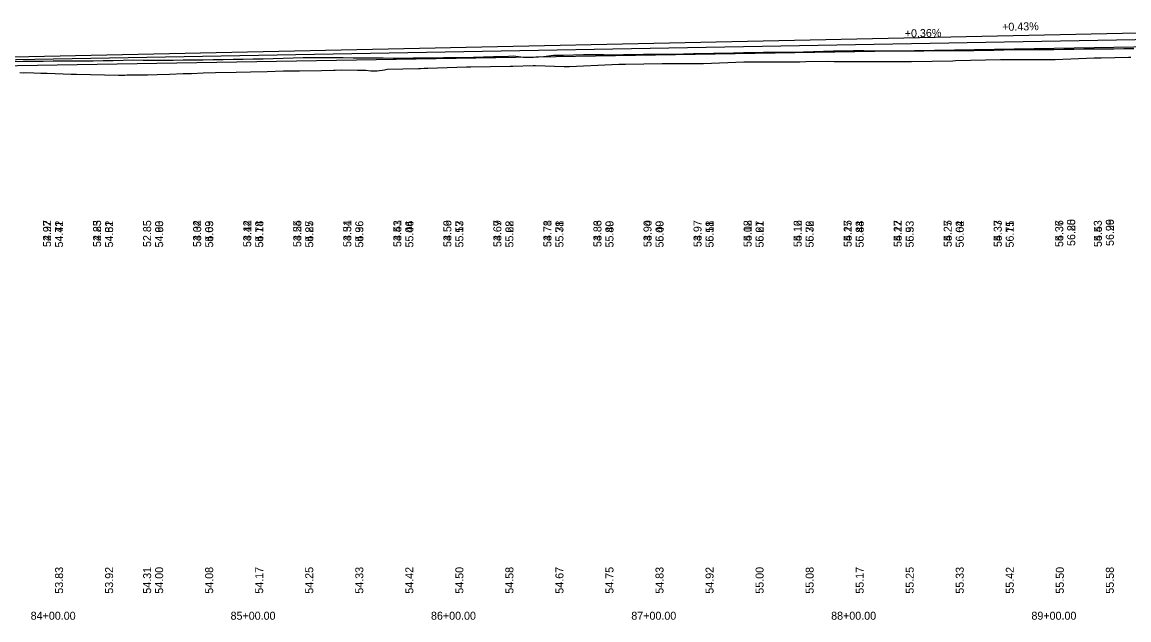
# Model space of a CAD drawing. Extents: x 3880794 to 3915434, y 287517 to 300173.
# Drawn here: x 3888923 to 3889476, y 296520 to 296818 of the extents above; entities that cross this region are included whole.
import ezdxf

# ---------------------------------------------------------------- set-up
doc = ezdxf.new("R2010")
doc.units = 0
for name, color, linetype in [('Level 1', 7, 'Continuous'), ('Level 2', 7, 'Continuous'), ('Level 30', 7, 'Continuous'), ('Level 31', 7, 'Continuous'), ('Level 32', 7, 'Continuous')]:
    doc.layers.add(name, color=color, linetype=linetype)

msp = doc.modelspace()

# ---------------------------------------------------------------- linework, layer by layer
at = {"layer": 'Level 1'}
for p, q in [((3888738.3, 296796.31), (3889688.3, 296813.2)), ((3888838.3, 296795.26), (3889488.3, 296806.09))]:
    msp.add_line(p, q, dxfattribs=at)
for points in [[(3889053.36, 296793.87), (3889061.46, 296793.9), (3889072.43, 296794.12), (3889078.43, 296794.26), (3889079.25, 296794.28), (3889082.36, 296794.35), (3889090.47, 296794.32), (3889094.53, 296794.25), (3889097.02, 296793.96), (3889100.25, 296793.83), (3889103.91, 296794.37), (3889105.27, 296794.68), (3889120.87, 296795.13), (3889121.85, 296795.15), (3889123.77, 296795.23), (3889124.54, 296795.26), (3889125.59, 296795.27), (3889144.89, 296795.92), (3889145.99, 296795.94), (3889146.96, 296795.95), (3889166.63, 296796.29), (3889167.97, 296796.21), (3889178.11, 296796.61), (3889179.3, 296796.56), (3889193.68, 296796.15), (3889196.34, 296796.11), (3889217.47, 296797.09), (3889220.9, 296797.22), (3889224.36, 296797.26), (3889242.67, 296797.49), (3889245.63, 296797.53), (3889263.27, 296797.61), (3889283.42, 296798.35), (3889286.81, 296798.35), (3889289.5, 296798.35), (3889311.1, 296798.48), (3889311.46, 296798.48), (3889314.35, 296798.58), (3889325.81, 296798.69), (3889328.48, 296798.63), (3889348.35, 296798.61), (3889351.29, 296798.6), (3889364.32, 296798.59), (3889367.22, 296798.58), (3889387.83, 296798.97), (3889389.24, 296799.06), (3889411.61, 296799.57), (3889413.01, 296799.6), (3889414.23, 296799.6), (3889414.78, 296799.63), (3889436.63, 296799.56), (3889437.3, 296799.58), (3889438, 296799.57), (3889438.99, 296799.56), (3889458.38, 296800.36), (3889459.5, 296800.35), (3889460.7, 296800.34), (3889461.94, 296800.36), (3889475.54, 296800.74), (3889476.79, 296800.77)], [(3888921.69, 296793.05), (3888923.47, 296792.97), (3888924.7, 296793), (3888928.75, 296792.84), (3888932.14, 296792.77), (3888935.35, 296792.76), (3888943.28, 296792.35), (3888947.42, 296792.29), (3888950.09, 296792.22), (3888970.95, 296791.72), (3888974.2, 296791.67), (3888975.18, 296791.99), (3888978.65, 296791.95), (3888985.44, 296791.95), (3888990.3, 296792.07), (3888996.4, 296792.18), (3889003.31, 296792.59), (3889007.41, 296792.65), (3889013.34, 296792.86), (3889019.53, 296793), (3889029.77, 296793.2), (3889036.94, 296793.42), (3889045.34, 296793.59), (3889053.36, 296793.87)]]:
    msp.add_lwpolyline(points, dxfattribs=at)
at = {"layer": 'Level 2'}
msp.add_line((3888738.3, 296797.04), (3889538.3, 296814.17), dxfattribs=at)
for points in [[(3889038.3, 296799.86), (3889043.3, 296799.98), (3889048.3, 296800.11), (3889053.3, 296800.24), (3889058.3, 296800.4), (3889063.3, 296800.5), (3889068.3, 296800.5), (3889073.3, 296800.51), (3889078.3, 296800.51), (3889083.3, 296800.52), (3889088.3, 296800.44), (3889093.3, 296800.45), (3889098.3, 296800.35), (3889103.3, 296800.33), (3889108.3, 296800.31), (3889113.3, 296800.29), (3889118.3, 296800.33), (3889123.3, 296800.39), (3889128.3, 296800.44), (3889133.3, 296800.5), (3889138.3, 296800.55), (3889143.3, 296800.61), (3889148.3, 296800.72), (3889153.3, 296800.87), (3889158.3, 296801.03), (3889163.3, 296801.09), (3889168.3, 296801.39), (3889173.3, 296800.66), (3889178.3, 296800.72), (3889183.3, 296801.14), (3889188.3, 296801.67), (3889193.3, 296801.77), (3889198.3, 296801.88), (3889203.3, 296801.99), (3889208.3, 296802.09), (3889213.3, 296802.03), (3889218.3, 296801.98), (3889223.3, 296802), (3889228.3, 296802.08), (3889233.3, 296802.2), (3889238.3, 296802.27), (3889243.3, 296802.25), (3889248.3, 296802.31), (3889253.3, 296802.42), (3889258.3, 296802.53), (3889263.3, 296802.6), (3889268.3, 296802.66), (3889273.3, 296802.75), (3889278.3, 296802.85), (3889283.3, 296802.99), (3889288.3, 296803.13), (3889293.3, 296803.23), (3889298.3, 296803.24), (3889303.3, 296803.23), (3889308.3, 296803.23), (3889313.3, 296803.33), (3889318.3, 296803.56), (3889323.3, 296803.72), (3889328.3, 296803.85), (3889333.3, 296803.97), (3889338.3, 296804.01), (3889343.3, 296803.98), (3889348.3, 296803.92), (3889353.3, 296803.87), (3889358.3, 296803.87), (3889363.3, 296803.86), (3889368.3, 296803.9), (3889373.3, 296803.96), (3889378.3, 296804), (3889383.3, 296804.04), (3889388.3, 296804.08), (3889393.3, 296804.11), (3889398.3, 296804.13), (3889403.3, 296804.16), (3889408.3, 296804.26), (3889413.3, 296804.4), (3889418.3, 296804.5), (3889423.3, 296804.52), (3889428.3, 296804.52), (3889433.3, 296804.54), (3889438.3, 296804.61), (3889443.3, 296804.68), (3889448.3, 296804.75), (3889453.3, 296804.83), (3889458.3, 296804.9), (3889463.3, 296804.92), (3889468.3, 296804.95), (3889473.3, 296805), (3889478.3, 296805)], [(3888918.3, 296798.55), (3888923.3, 296798.74), (3888928.3, 296798.77), (3888933.3, 296798.81), (3888938.3, 296798.85), (3888943.3, 296798.89), (3888948.3, 296798.93), (3888953.3, 296798.92), (3888958.3, 296798.88), (3888963.3, 296799.01), (3888968.3, 296799.14), (3888973.3, 296799.27), (3888978.3, 296799.34), (3888983.3, 296799.31), (3888988.3, 296799.28), (3888993.3, 296799.25), (3888998.3, 296799.22), (3889003.3, 296799.32), (3889008.3, 296799.39), (3889013.3, 296799.47), (3889018.3, 296799.54), (3889023.3, 296799.61), (3889028.3, 296799.66), (3889033.3, 296799.73), (3889038.3, 296799.86)]]:
    msp.add_lwpolyline(points, dxfattribs=at)

# ---------------------------------------------------------------- texts
for s, rotation, p in [('+0.43%', 1.2269, (3889412.51, 296813.85)), ('54.71', 90, (3888943.3, 296705.66)), ('54.82', 90, (3888968.3, 296705.66)), ('54.93', 90, (3888993.3, 296705.66)), ('55.03', 90, (3889018.3, 296705.66)), ('55.14', 90, (3889043.3, 296705.66)), ('55.25', 90, (3889068.3, 296705.66)), ('55.36', 90, (3889093.3, 296705.66)), ('55.46', 90, (3889118.3, 296705.66)), ('55.57', 90, (3889143.3, 296705.66)), ('55.68', 90, (3889168.3, 296705.66)), ('55.78', 90, (3889193.3, 296705.66)), ('55.89', 90, (3889218.3, 296705.66)), ('56.00', 90, (3889243.3, 296705.66)), ('56.11', 90, (3889268.3, 296705.66)), ('56.21', 90, (3889293.3, 296705.66)), ('56.32', 90, (3889318.3, 296705.66)), ('56.43', 90, (3889343.3, 296705.66)), ('56.53', 90, (3889368.3, 296705.66)), ('56.64', 90, (3889393.3, 296705.66)), ('56.75', 90, (3889418.3, 296705.66)), ('56.85', 90, (3889449, 296706.43)), ('56.96', 90, (3889468.3, 296706.43))]:
    msp.add_text(s, height=4, rotation=rotation, dxfattribs=at).set_placement(p)
for s, p in [('84+00.00', (3888927.12, 296519.76)), ('85+00.00', (3889026.99, 296519.76)), ('86+00.00', (3889127.12, 296519.76)), ('87+00.00', (3889227.21, 296519.76)), ('88+00.00', (3889327.05, 296519.76)), ('89+00.00', (3889427.12, 296519.76))]:
    msp.add_text(s, height=4, dxfattribs=at).set_placement(p)
at = {"layer": 'Level 30'}
for s, p in [('52.97', (3888937.3, 296705.91)), ('52.83', (3888962.3, 296705.91)), ('52.85', (3888987.3, 296705.91)), ('53.02', (3889012.3, 296705.91)), ('53.14', (3889037.3, 296705.91)), ('53.24', (3889062.3, 296705.91)), ('53.31', (3889087.3, 296705.91)), ('53.43', (3889112.3, 296705.91)), ('53.59', (3889137.3, 296705.91)), ('53.69', (3889162.3, 296705.91)), ('53.71', (3889187.3, 296705.91)), ('53.83', (3889212.3, 296705.91)), ('53.94', (3889237.3, 296705.91)), ('53.97', (3889262.3, 296705.91)), ('54.12', (3889287.3, 296705.91)), ('54.16', (3889312.3, 296705.91)), ('54.17', (3889337.3, 296705.91)), ('54.17', (3889362.3, 296705.91)), ('54.25', (3889387.3, 296705.91)), ('54.37', (3889412.3, 296705.91)), ('54.36', (3889443, 296705.91)), ('54.53', (3889462.3, 296705.91))]:
    msp.add_text(s, height=4, rotation=90, dxfattribs=at).set_placement(p)
for s, p in [('84+00.00', (3888927.12, 296519.76)), ('84+00.00', (3888927.12, 296519.76)), ('84+00.00', (3888927.12, 296519.76)), ('85+00.00', (3889026.99, 296519.76)), ('85+00.00', (3889026.99, 296519.76)), ('85+00.00', (3889026.99, 296519.76)), ('86+00.00', (3889127.12, 296519.76)), ('86+00.00', (3889127.12, 296519.76)), ('86+00.00', (3889127.12, 296519.76)), ('87+00.00', (3889227.21, 296519.76)), ('87+00.00', (3889227.21, 296519.76)), ('87+00.00', (3889227.21, 296519.76)), ('88+00.00', (3889327.05, 296519.76)), ('88+00.00', (3889327.05, 296519.76)), ('88+00.00', (3889327.05, 296519.76)), ('89+00.00', (3889427.12, 296519.76)), ('89+00.00', (3889427.12, 296519.76)), ('89+00.00', (3889427.12, 296519.76))]:
    msp.add_text(s, height=4, dxfattribs=at).set_placement(p)
at = {"layer": 'Level 31'}
for s, rotation, p in [('+0.36%', 1.0185, (3889363.86, 296810.59)), ('54.42', 90, (3888943.3, 296705.66)), ('54.51', 90, (3888968.3, 296705.66)), ('54.60', 90, (3888993.3, 296705.66)), ('54.69', 90, (3889018.3, 296705.66)), ('54.78', 90, (3889043.3, 296705.66)), ('54.87', 90, (3889068.3, 296705.66)), ('54.96', 90, (3889093.3, 296705.66)), ('55.04', 90, (3889118.3, 296705.66)), ('55.13', 90, (3889143.3, 296705.66)), ('55.22', 90, (3889168.3, 296705.66)), ('55.31', 90, (3889193.3, 296705.66)), ('55.40', 90, (3889218.3, 296705.66)), ('55.49', 90, (3889243.3, 296705.66)), ('55.58', 90, (3889268.3, 296705.66)), ('55.67', 90, (3889293.3, 296705.66)), ('55.76', 90, (3889318.3, 296705.66)), ('55.84', 90, (3889343.3, 296705.66)), ('55.93', 90, (3889368.3, 296705.66)), ('56.02', 90, (3889393.3, 296705.66)), ('56.11', 90, (3889418.3, 296705.66)), ('56.20', 90, (3889449, 296706.43)), ('56.29', 90, (3889468.3, 296706.43)), ('53.83', 90, (3888943.3, 296532.76)), ('53.92', 90, (3888968.3, 296532.76)), ('54.00', 90, (3888993.3, 296532.76)), ('54.08', 90, (3889018.3, 296532.76)), ('54.17', 90, (3889043.3, 296532.76)), ('54.25', 90, (3889068.3, 296532.76)), ('54.33', 90, (3889093.3, 296532.76)), ('54.42', 90, (3889118.3, 296532.76)), ('54.50', 90, (3889143.3, 296532.76)), ('54.58', 90, (3889168.3, 296532.76)), ('54.67', 90, (3889193.3, 296532.76)), ('54.75', 90, (3889218.3, 296532.76)), ('54.83', 90, (3889243.3, 296532.76)), ('54.92', 90, (3889268.3, 296532.76)), ('55.00', 90, (3889293.3, 296532.76)), ('55.08', 90, (3889318.3, 296532.76)), ('55.17', 90, (3889343.3, 296532.76)), ('55.25', 90, (3889368.3, 296532.76)), ('55.33', 90, (3889393.3, 296532.76)), ('55.42', 90, (3889418.3, 296532.76)), ('55.50', 90, (3889443.3, 296532.76)), ('55.58', 90, (3889468.3, 296532.76))]:
    msp.add_text(s, height=4, rotation=rotation, dxfattribs=at).set_placement(p)
at = {"layer": 'Level 32'}
for s, p in [('54.22', (3888937.3, 296705.91)), ('54.25', (3888962.3, 296705.91)), ('54.34', (3889012.3, 296705.91)), ('54.42', (3889037.3, 296705.91)), ('54.55', (3889062.3, 296705.91)), ('54.54', (3889087.3, 296705.91)), ('54.51', (3889112.3, 296705.91)), ('54.56', (3889137.3, 296705.91)), ('54.67', (3889162.3, 296705.91)), ('54.78', (3889187.3, 296705.91)), ('54.86', (3889212.3, 296705.91)), ('54.90', (3889237.3, 296705.91)), ('54.97', (3889262.3, 296705.91)), ('55.08', (3889287.3, 296705.91)), ('55.12', (3889312.3, 296705.91)), ('55.25', (3889337.3, 296705.91)), ('55.22', (3889362.3, 296705.91)), ('55.27', (3889387.3, 296705.91)), ('55.33', (3889412.3, 296705.91)), ('55.37', (3889443, 296705.91)), ('55.43', (3889462.3, 296705.91)), ('54.31', (3888987.3, 296532.76))]:
    msp.add_text(s, height=4, rotation=90, dxfattribs=at).set_placement(p)

doc.saveas('drawing.dxf')
